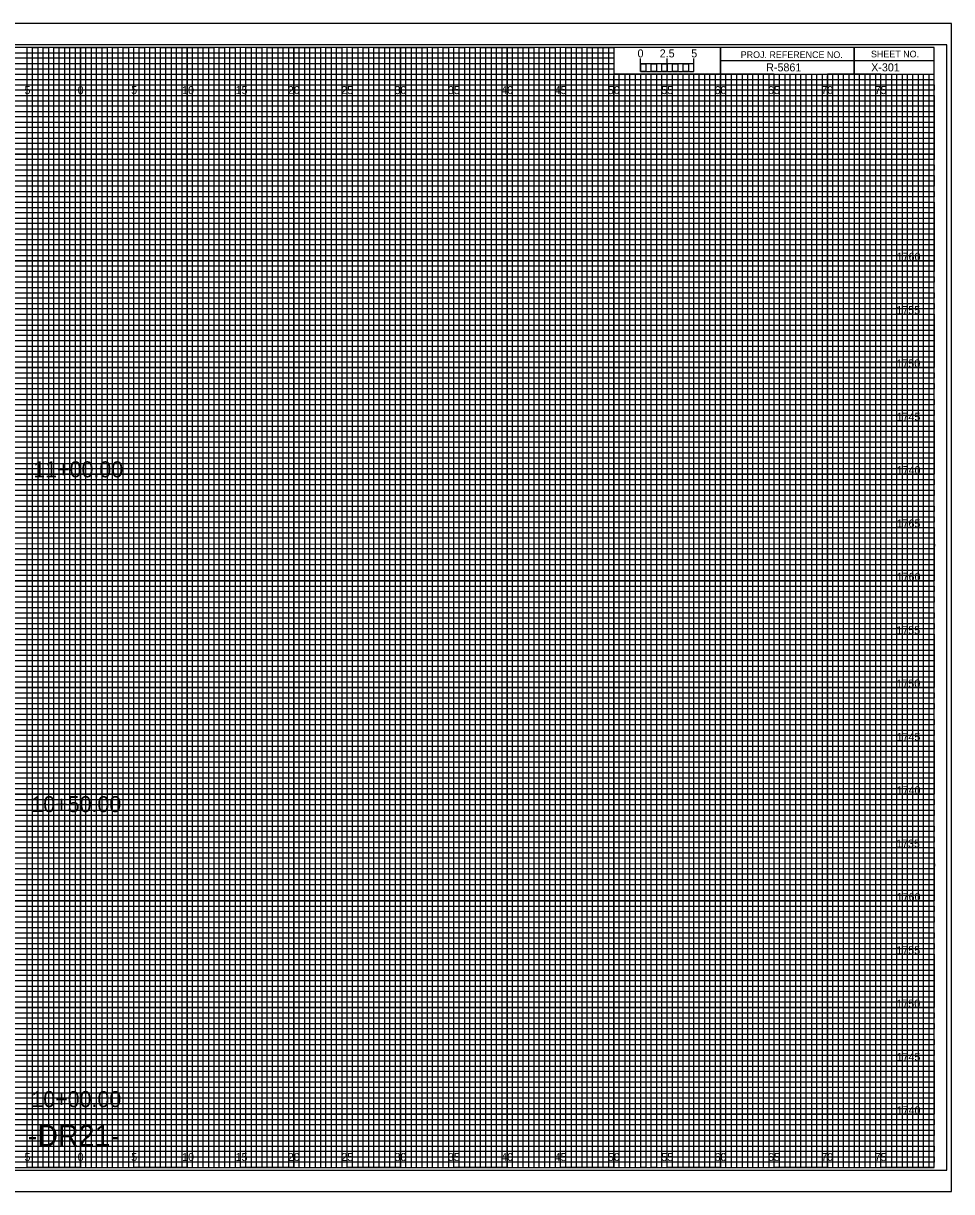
# Model space of a CAD drawing. Extents: x -7 to 162, y -2 to 107.
# Drawn here: x 74.6 to 161.7, y -2.3 to 107.3 of the extents above; entities that cross this region are included whole.
import ezdxf

# ---------------------------------------------------------------- set-up
doc = ezdxf.new("R2010")
doc.units = 0
for name, color, linetype in [('Prop XS Alignment Label', 7, 'Continuous'), ('Prop XS Bar Scale Labels', 7, 'Continuous'), ('Prop XS Elevation Labels', 7, 'Continuous'), ('Prop XS Offset Labels', 7, 'Continuous'), ('Prop XS Project Number', 7, 'Continuous'), ('Prop XS Sheet Number', 7, 'Continuous'), ('Prop XS Station Labels', 7, 'Continuous'), ('Sheet Cross Section CELL', 7, 'Continuous'), ('Sheet Cross Section Grid Major CELL', 7, 'Continuous'), ('Sheet Cross Section Grid Middle CELL', 7, 'Continuous'), ('Sheet Cross Section Grid Minor 1 CELL', 7, 'Continuous'), ('Sheet Cross Section Grid Minor 2 CELL', 7, 'Continuous'), ('Sheet Cross Section Scale CELL', 7, 'Continuous'), ('Sheet Cutting Line CELL', 7, 'Continuous'), ('Sheet DOT Grid CELL', 7, 'Continuous'), ('Sheet Plot Border Inside CELL', 7, 'Continuous'), ('Sheet Plot Border Outside CELL', 7, 'Continuous')]:
    doc.layers.add(name, color=color, linetype=linetype)

msp = doc.modelspace()

# ---------------------------------------------------------------- linework, layer by layer
at = {"layer": 'Sheet Cross Section CELL'}
for p, q in [((152.5, 105), (152.5, 102.5)), ((152.5, 102.5), (152.5, 105)), ((160, 103.75), (140, 103.75)), ((140, 103.75), (140, 102.5)), ((140, 102.5), (160, 102.5))]:
    msp.add_line(p, q, dxfattribs=at)
for points in [[(160, 105), (0, 105), (0, 0), (160, 0)], [(140, 105), (130, 105), (130, 102.52), (140, 102.52)], [(160, 105), (140, 105), (140, 102.5), (160, 102.5)]]:
    msp.add_lwpolyline(points, close=True, dxfattribs=at)
at = {"layer": 'Sheet Cross Section Grid Major CELL'}
for p, q in [((75, 105), (70, 105)), ((75, 0), (75, 105)), ((85, 105), (80, 105)), ((80, 105), (80, 0)), ((85, 0), (85, 105)), ((95, 105), (90, 105)), ((90, 105), (90, 0)), ((95, 0), (95, 105)), ((105, 105), (100, 105)), ((100, 105), (100, 0)), ((105, 0), (105, 105)), ((115, 105), (110, 105)), ((110, 105), (110, 0)), ((115, 0), (115, 105)), ((125, 105), (120, 105)), ((120, 105), (120, 0)), ((125, 0), (125, 105)), ((130, 105), (130, 0)), ((135, 0), (135, 102.5)), ((145, 102.5), (140, 102.5)), ((140, 102.5), (140, 0)), ((145, 0), (145, 102.5)), ((155, 102.5), (150, 102.5)), ((150, 102.5), (150, 0)), ((155, 0), (155, 102.5)), ((80, 0), (75, 0)), ((90, 0), (85, 0)), ((100, 0), (95, 0)), ((110, 0), (105, 0)), ((120, 0), (115, 0)), ((130, 0), (125, 0)), ((140, 0), (135, 0)), ((150, 0), (145, 0)), ((160, 0), (155, 0)), ((160, 0), (160, 0))]:
    msp.add_line(p, q, dxfattribs=at)
for points in [[(0, 100), (160, 100), (160, 95), (0, 95)], [(0, 90), (160, 90), (160, 85), (0, 85)], [(0, 80), (160, 80), (160, 75), (0, 75)], [(0, 70), (160, 70), (160, 65), (0, 65)], [(0, 60), (160, 60), (160, 55), (0, 55)], [(0, 50), (160, 50), (160, 45), (0, 45)], [(0, 40), (160, 40), (160, 35), (0, 35)], [(0, 30), (160, 30), (160, 25), (0, 25)], [(0, 20), (160, 20), (160, 15), (0, 15)], [(0, 10), (160, 10), (160, 5), (0, 5)]]:
    msp.add_lwpolyline(points, dxfattribs=at)
at = {"layer": 'Sheet Cross Section Grid Middle CELL'}
for points in [[(72.5, 0), (77.5, 0), (77.5, 105), (82.5, 105), (82.5, 0), (87.5, 0), (87.5, 105), (92.5, 105), (92.5, 0), (97.5, 0), (97.5, 105), (102.5, 105), (102.5, 0), (107.5, 0), (107.5, 105), (112.5, 105), (112.5, 0), (117.5, 0), (117.5, 105), (122.5, 105), (122.5, 0), (127.5, 0), (127.5, 105), (129.97, 105), (130, 105), (130, 102.5), (132.5, 102.5), (132.5, 0), (137.5, 0), (137.5, 102.5), (142.5, 102.5), (142.5, 0), (147.5, 0), (147.5, 102.5), (152.5, 102.5), (152.5, 0), (157.5, 0), (157.5, 102.5)], [(0, 102.5), (137.5, 102.5)], [(0, 92.5), (160, 92.5), (160, 97.5), (0, 97.5)], [(0, 82.5), (160, 82.5), (160, 87.5), (0, 87.5)], [(0, 72.5), (160, 72.5), (160, 77.5), (0, 77.5)], [(0, 62.5), (160, 62.5), (160, 67.5), (0, 67.5)], [(0, 52.5), (160, 52.5), (160, 57.5), (0, 57.5)], [(0, 42.5), (160, 42.5), (160, 47.5), (0, 47.5)], [(0, 32.5), (160, 32.5), (160, 37.5), (0, 37.5)], [(0, 22.5), (160, 22.5), (160, 27.5), (0, 27.5)], [(0, 12.5), (160, 12.5), (160, 17.5), (0, 17.5)], [(0, 2.5), (160, 2.5), (160, 7.5), (0, 7.5)]]:
    msp.add_lwpolyline(points, dxfattribs=at)
at = {"layer": 'Sheet Cross Section Grid Minor 1 CELL'}
for p, q in [((0, 104.5), (130, 104.5)), ((130, 104.5), (130, 103.99)), ((130, 103.99), (0, 103.99)), ((0, 103.5), (130, 103.5)), ((130, 102.95), (0, 102.95)), ((130, 103.5), (130, 102.95)), ((0, 102), (160, 102))]:
    msp.add_line(p, q, dxfattribs=at)
for points in [[(0, 101.5), (135, 101.5), (160, 101.5), (160, 101), (0, 101)], [(0, 100.5), (160, 100.5), (160, 99.5), (0, 99.5)], [(0, 99), (160, 99), (160, 98.5), (0, 98.49)], [(0, 98), (160, 98), (160, 97), (0, 97)], [(0, 96.5), (160, 96.5), (160, 96), (0, 96)], [(0, 95.5), (160, 95.5), (160, 94.5), (0, 94.5)], [(0, 94), (160, 94), (160, 93.5), (0, 93.5)], [(0, 93), (160, 93), (160, 92), (0, 92)], [(0, 91.5), (160, 91.5), (160, 91), (0, 91)], [(0, 90.5), (160, 90.5), (160, 89.5), (0, 89.5)], [(0, 89), (160, 89), (160, 88.5), (0, 88.5)], [(0, 88), (160, 88), (160, 86.98), (160, 86.5), (160, 86), (0, 86)], [(0, 87), (160, 87), (160, 86.5), (0, 86.5)], [(0, 85.5), (160, 85.5), (160, 84.5), (0, 84.52)], [(0, 84.52), (160, 84.5), (160, 84), (0, 84)], [(0, 83.5), (160, 83.5), (160, 83), (0, 83)], [(0, 82), (160, 82), (160, 81.5), (0, 81.5)], [(0, 81), (160, 81), (160, 80.5), (0, 80.5)], [(-0.04, 79.45), (160, 79.45), (160, 78.94), (-0.04, 78.94)], [(0, 78.5), (160, 78.5), (160, 78), (0, 78)], [(0, 77), (160, 77), (160, 76.5), (0, 76.5)], [(0, 76), (160, 76), (160, 75.5), (0, 75.5)], [(0, 74.5), (160, 74.5), (160, 74), (0, 74)], [(0, 73.5), (160, 73.5), (160, 73), (0, 73)], [(0, 72), (160, 72), (160, 71.5), (0, 71.5)], [(0, 71), (160, 71), (160, 70.5), (0, 70.5)], [(0, 69.5), (160, 69.5), (160, 68.99), (0, 69)], [(0, 68.5), (160, 68.5), (160, 68), (0, 68)], [(0, 67), (160, 67), (160, 66.5), (0, 66.5)], [(0, 66), (160, 66), (160, 65.5), (0, 65.5)], [(0, 64.5), (160, 64.5), (160, 64), (0, 64)], [(0, 63.5), (160, 63.5), (160, 63), (0, 63)], [(0, 62), (160, 62), (160, 61.5), (0, 61.5)], [(0, 61), (160, 61), (160, 60.5), (0, 60.5)], [(0, 59.5), (160, 59.5), (160, 59), (0, 59)], [(0, 58.5), (160.03, 58.45), (160, 58), (0, 58)], [(0, 57), (160, 57), (160, 56.5), (0, 56.5)], [(0, 56), (160, 56), (160, 55.5), (0, 55.5)], [(0, 54.5), (160, 54.5), (160, 54), (0, 54)], [(0, 53.5), (160, 53.5), (160, 53), (0, 53)], [(0, 52), (160, 52), (160, 51.5), (0, 51.5)], [(0, 51), (160, 51), (160, 50.5), (0, 50.5)], [(0, 49.5), (160, 49.5), (160, 49), (0, 49)], [(0, 48.5), (160, 48.5), (160, 48), (0, 48)], [(0, 47), (160, 47), (160, 46.5), (0, 46.5)], [(0, 46), (160, 46), (160, 45.5), (0, 45.5)], [(0, 44.5), (160, 44.5), (160, 44), (0, 44)], [(0, 43.5), (160, 43.5), (160, 43), (0, 43)], [(0, 42), (160, 42), (160, 41.5), (0, 41.5)], [(0, 41), (160, 41), (160, 40.5), (0, 40.5)], [(0, 39.5), (160, 39.5), (160, 38.99), (0, 39)], [(0, 38.5), (160, 38.5), (160, 38), (0, 38)], [(0, 37), (160, 37), (160, 36.5), (0, 36.5)], [(0, 36), (160, 36), (160, 35.5), (0, 35.5)], [(0, 34.5), (160, 34.5), (160, 34), (0, 34)], [(0, 33.5), (160, 33.5), (160, 33), (0, 33)], [(0, 32), (160, 32), (160, 31.5), (0, 31.5)], [(0, 31), (160, 31), (160, 30.5), (0, 30.5)], [(0, 29.5), (160, 29.5), (160, 29), (0, 29)], [(0, 28.5), (160.03, 28.46), (160, 28), (0, 28)], [(0, 27), (160, 27), (160, 26.5), (0, 26.5)], [(0, 26), (160, 26), (160, 25.5), (0, 25.5)], [(0, 24.5), (160, 24.5), (160, 24), (0, 24)], [(0, 23.5), (160, 23.5), (160, 23), (0, 23)], [(0, 22), (160, 22), (160, 21.5), (0, 21.5)], [(0, 21), (160, 21), (160, 20.5), (0, 20.5)], [(0, 19.5), (160, 19.5), (160, 19), (0, 19)], [(0, 18.5), (160, 18.5), (160, 18), (0, 18)], [(0, 17), (160, 17), (160, 16.5), (0, 16.5)], [(0, 16), (160, 16), (160, 15.5), (0, 15.5)], [(0, 14.5), (160, 14.5), (160, 14), (0, 14)], [(0, 13.5), (160, 13.5), (160, 13), (0, 13)], [(0, 12), (160, 12), (160, 11.5), (0, 11.5)], [(0, 11), (160, 11), (160, 10.5), (0, 10.5)], [(0, 9.5), (160, 9.5), (160, 9), (0, 9)], [(0, 8.5), (160, 8.5), (160, 8), (0, 8)], [(0, 7), (160, 7), (160, 6.5), (0, 6.5)], [(0, 6), (160, 6), (160, 5.5), (0, 5.5)], [(0, 4.5), (160, 4.5), (160, 4), (0, 4)], [(0, 3.5), (160, 3.5), (160, 3), (0, 3)], [(0, 2), (160, 2), (160, 1.5), (0, 1.5)], [(0, 1), (160, 1), (160, 0.5), (0, 0.5)]]:
    msp.add_lwpolyline(points, dxfattribs=at)
at = {"layer": 'Sheet Cross Section Grid Minor 2 CELL'}
for p, q in [((133.5, 102.5), (133, 102.5)), ((133, 102.5), (133, 0)), ((133.5, 0), (133.5, 102.5)), ((134.5, 102.5), (134, 102.5)), ((134, 102.5), (134, 0)), ((134.5, 0), (134.5, 102.5)), ((133, 0), (132.5, 0)), ((134, 0), (133.5, 0))]:
    msp.add_line(p, q, dxfattribs=at)
for points in [[(75, 0), (75.5, 0), (75.5, 105), (76, 105), (76, 0)], [(76, 0), (76.5, 0), (76.5, 105), (77, 105), (77, 0)], [(77.5, 0), (78, 0), (78, 105), (78.5, 105), (78.5, 0)], [(78.5, 0), (79, 0), (79, 105), (79.5, 105), (79.5, 0)], [(80, 0), (80.5, 0), (80.5, 105), (81, 105), (81, 0)], [(81, 0), (81.5, 0), (81.5, 105), (82, 105), (82, 0)], [(82.5, 0), (83, 0), (83, 105), (83.5, 105), (83.5, 0)], [(83.5, 0), (84, 0), (84, 105), (84.5, 105), (84.5, 0)], [(85, 0), (85.5, 0), (85.5, 105), (86, 105), (86, 0)], [(86, 0), (86.5, 0), (86.5, 105), (87, 105), (87, 0)], [(87.5, 0), (88, 0), (88, 105), (88.5, 105), (88.5, 0)], [(88.5, 0), (89, 0), (89, 105), (89.5, 105), (89.5, 0)], [(90, 0), (90.5, 0), (90.5, 105), (91, 105), (91, 0)], [(91, 0), (91.5, 0), (91.5, 105), (92, 105), (92, 0)], [(92.5, 0), (93, 0), (93, 105), (93.5, 105), (93.5, 0)], [(93.5, 0), (94, 0), (94, 105), (94.5, 105), (94.5, 0)], [(95, 0), (95.5, 0), (95.5, 105), (96, 105), (96, 0)], [(96, 0), (96.5, 0), (96.5, 105), (97, 105), (97, 0)], [(97.5, 0), (98, 0), (98, 105), (98.5, 105), (98.5, 0)], [(98.5, 0), (99, 0), (99, 105), (99.5, 105), (99.5, 0)], [(100, 0), (100.5, 0), (100.5, 105), (101, 105), (101, 0)], [(101, 0), (101.5, 0), (101.5, 105), (102, 105), (102, 0)], [(102.5, 0), (103, 0), (103, 105), (103.5, 105), (103.5, 0)], [(103.5, 0), (104, 0), (104, 105), (104.5, 105), (104.5, 0)], [(105, 0), (105.5, 0), (105.5, 105), (106, 105), (106, 0)], [(106, 0), (106.5, 0), (106.5, 105), (107, 105), (107, 0)], [(107.5, 0), (108, 0), (108, 105), (108.5, 105), (108.5, 0)], [(108.5, 0), (109, 0), (109, 105), (109.5, 105), (109.5, 0)], [(110, 0), (110.5, 0), (110.5, 105), (111, 105), (111, 0)], [(111, 0), (111.5, 0), (111.5, 105), (112, 105), (112, 0)], [(112.5, 0), (113, 0), (113, 105), (113.5, 105), (113.5, 0)], [(113.5, 0), (114, 0), (114, 105), (114.5, 105), (114.5, 0)], [(115, 0), (115.5, 0), (115.5, 105), (116, 105), (116, 0)], [(116, 0), (116.5, 0), (116.5, 105), (117, 105), (117, 0)], [(117.5, 0), (118, 0), (118, 105), (118.5, 105), (118.5, 0)], [(118.5, 0), (119, 0), (119, 105), (119.5, 105), (119.5, 0)], [(120, 0), (120.5, 0), (120.5, 105), (121, 105), (121, 0)], [(121, 0), (121.5, 0), (121.5, 105), (122, 105), (122, 0)], [(122.5, 0), (123, 0), (123, 105), (123.5, 105), (123.5, 0)], [(123.5, 0), (124, 0), (124, 105), (124.5, 105), (124.5, 0)], [(125, 0), (125.5, 0), (125.5, 105), (126, 105), (126, 0)], [(126, 0), (126.5, 0), (126.5, 105), (127, 105), (127, 0)], [(127.5, 0), (128, 0), (128, 105), (128.5, 105), (128.5, 0)], [(128.5, 0), (129, 0), (129, 105), (129.5, 105), (129.5, 0)], [(130, 0), (130.5, 0), (130.5, 102.5), (131.01, 102.5), (131.01, 0)], [(131, 0), (131.5, 0), (131.5, 102.5), (132, 102.5), (132, 0)], [(135, 0), (135.49, 0), (135.49, 102.5), (136, 102.5), (136, 0)], [(136, 0), (136.5, 0), (136.5, 102.5), (137.03, 102.5), (137.03, 0)], [(137.5, 0), (138, 0), (138, 102.5), (138.5, 102.5), (138.5, 0)], [(138.5, 0), (139, 0), (139, 102.5), (139.5, 102.5), (139.5, 0)], [(140, 0), (140.5, 0), (140.5, 102.5), (141, 102.5), (141, 0)], [(141, 0), (141.5, 0), (141.5, 102.5), (142, 102.5), (142, 0)], [(142.5, 0), (143, 0), (143, 102.5), (143.5, 102.5), (143.5, 0)], [(143.5, 0), (144, 0), (144, 102.5), (144.5, 102.5), (144.5, 0)], [(145, 0), (145.5, 0), (145.5, 102.5), (146, 102.5), (146, 0)], [(146, 0), (146.5, 0), (146.5, 102.5), (147, 102.5), (147, 0)], [(147.5, 0), (148, 0), (148, 102.5), (148.5, 102.5), (148.5, 0)], [(148.5, 0), (149, 0), (149, 102.5), (149.5, 102.5), (149.5, 0)], [(150, 0), (150.5, 0), (150.5, 102.5), (151, 102.5), (151, 0)], [(151, 0), (151.5, 0), (151.5, 102.5), (152, 102.5), (152, 0)], [(152.5, 0), (153, 0), (153, 102.5), (153.5, 102.5), (153.5, 0)], [(153.5, 0), (154, 0), (154, 102.5), (154.5, 102.5), (154.5, 0)], [(155, 0), (155.5, 0), (155.5, 102.5), (156, 102.5), (156, 0)], [(156, 0), (156.5, 0), (156.5, 102.5), (157, 102.5), (157, 0)], [(157.5, 0), (158, 0), (158, 102.5), (158.5, 102.5), (158.5, 0)], [(158.5, 0), (159, 0), (159, 102.5), (159.5, 102.5), (159.5, 0)]]:
    msp.add_lwpolyline(points, dxfattribs=at)
at = {"layer": 'Sheet Cross Section Scale CELL'}
for p, q in [((132.5, 102.75), (132.5, 103.95)), ((132.5, 103.45), (132.5, 103.95)), ((135, 102.75), (135, 103.95)), ((137.5, 102.75), (137.5, 103.95)), ((137.5, 103.45), (137.5, 103.95))]:
    msp.add_line(p, q, dxfattribs=at)
for points in [[(137.5, 103.45), (132.5, 103.45), (132.5, 102.75), (137.5, 102.75)], [(132.5, 103.45), (133, 103.45), (133, 102.75), (132.5, 102.75)], [(133.5, 103.45), (134, 103.45), (134, 102.75), (133.5, 102.75)], [(134.5, 103.45), (135, 103.45), (135, 102.75), (134.5, 102.75)], [(135.5, 103.45), (136, 103.45), (136, 102.75), (135.5, 102.75)], [(136.5, 103.45), (137, 103.45), (137, 102.75), (136.5, 102.75)]]:
    msp.add_lwpolyline(points, close=True, dxfattribs=at)
at = {"layer": 'Sheet Cutting Line CELL'}
for p, q in [((161.65, 107.25), (-6.7, 107.25)), ((-6.7, -2.25), (161.65, -2.25))]:
    msp.add_line(p, q, dxfattribs=at)
at = {"layer": 'Sheet DOT Grid CELL'}
for p, q in [((75, 0), (75, 105)), ((80, 0), (80, 105)), ((85, 0), (85, 105)), ((90, 0), (90, 105)), ((95, 0), (95, 105)), ((100, 0), (100, 105)), ((105, 0), (105, 105)), ((110, 0), (110, 105)), ((115, 0), (115, 105)), ((120, 0), (120, 105)), ((125, 0), (125, 105)), ((130, 0), (130, 102.34)), ((135, 0), (135, 102.34)), ((140, 0), (140, 102.34)), ((145, 0), (145, 102.34)), ((150, 0), (150, 102.34)), ((155, 0), (155, 102.34)), ((0, 100), (160, 100)), ((0, 95), (160, 95)), ((0, 90), (160, 90)), ((0, 85), (160, 85)), ((0, 80), (160, 80)), ((0, 75), (160, 75)), ((0, 70), (160, 70)), ((0, 65), (160, 65)), ((0, 60), (160, 60)), ((0, 55), (160, 55)), ((0, 50), (160, 50)), ((0, 45), (160, 45)), ((0, 40), (160, 40)), ((0, 35), (160, 35)), ((0, 30), (160, 30)), ((0, 25), (160, 25)), ((0, 20), (160, 20)), ((0, 15), (160, 15)), ((0, 10), (160, 10)), ((0, 5), (160, 5))]:
    msp.add_line(p, q, dxfattribs=at)
at = {"layer": 'Sheet Plot Border Inside CELL'}
msp.add_lwpolyline([(-5.4, -0.25), (161.2, -0.25), (161.2, 105.25), (-5.4, 105.25)], close=True, dxfattribs=at)
at = {"layer": 'Sheet Plot Border Outside CELL'}
msp.add_lwpolyline([(-6.7, -2.25), (161.65, -2.25), (161.65, 107.25), (-6.7, 107.25)], close=True, dxfattribs=at)

# ---------------------------------------------------------------- texts
at = {"layer": 'Prop XS Alignment Label'}
msp.add_text('-DR21-', height=2, dxfattribs=at).set_placement((75.06, 2))
at = {"layer": 'Prop XS Bar Scale Labels'}
for s, p in [('2.5', (134.29, 104.06)), ('5', (137.24, 104.06))]:
    msp.add_text(s, height=0.75, dxfattribs=at).set_placement(p)
at = {"layer": 'Prop XS Elevation Labels'}
for s, p in [('1760', (156.5, 85)), ('1755', (156.47, 80)), ('1750', (156.48, 75)), ('1745', (156.49, 70)), ('1740', (156.5, 65)), ('1765', (156.49, 60)), ('1760', (156.5, 55)), ('1755', (156.47, 50)), ('1750', (156.48, 45)), ('1745', (156.49, 40)), ('1740', (156.5, 35)), ('1735', (156.45, 30)), ('1760', (156.5, 25)), ('1755', (156.47, 20)), ('1750', (156.48, 15)), ('1745', (156.49, 10)), ('1740', (156.5, 5))]:
    msp.add_text(s, height=0.75, dxfattribs=at).set_placement(p)
at = {"layer": 'Prop XS Offset Labels'}
for s, p in [('5', (74.74, 100.62)), ('0', (79.73, 100.62)), ('0', (79.73, 100.62)), ('5', (84.74, 100.62)), ('10', (89.52, 100.62)), ('15', (94.53, 100.62)), ('20', (99.43, 100.62)), ('25', (104.44, 100.62)), ('30', (109.43, 100.62)), ('35', (114.44, 100.62)), ('40', (119.43, 100.62)), ('45', (124.44, 100.62)), ('50', (129.43, 100.62)), ('55', (134.44, 100.62)), ('60', (139.43, 100.62)), ('65', (144.44, 100.62)), ('70', (149.43, 100.62)), ('75', (154.44, 100.62)), ('5', (74.74, 0.62)), ('0', (79.73, 0.62)), ('0', (79.73, 0.62)), ('5', (84.74, 0.62)), ('10', (89.52, 0.62)), ('15', (94.53, 0.62)), ('20', (99.43, 0.62)), ('25', (104.44, 0.62)), ('30', (109.43, 0.62)), ('35', (114.44, 0.62)), ('40', (119.43, 0.62)), ('45', (124.44, 0.62)), ('50', (129.43, 0.62)), ('55', (134.44, 0.62)), ('60', (139.43, 0.62)), ('65', (144.44, 0.62)), ('70', (149.43, 0.62)), ('75', (154.44, 0.62))]:
    msp.add_text(s, height=0.75, dxfattribs=at).set_placement(p)
at = {"layer": 'Prop XS Project Number'}
msp.add_text('R-5861', height=0.75, dxfattribs=at).set_placement((144.27, 102.75))
at = {"layer": 'Prop XS Sheet Number'}
msp.add_text('X-301', height=0.75, dxfattribs=at).set_placement((154.11, 102.75))
at = {"layer": 'Prop XS Station Labels'}
for s, p in [('11+00.00', (75.57, 64.7)), ('10+50.00', (75.39, 33.32)), ('10+00.00', (75.39, 5.67))]:
    msp.add_text(s, height=1.5, dxfattribs=at).set_placement(p)
at = {"layer": 'Sheet Cross Section CELL'}
for s, p in [('PROJ. REFERENCE NO.', (141.88, 104)), ('SHEET NO.', (154.09, 104.06))]:
    msp.add_text(s, height=0.625, dxfattribs=at).set_placement(p)
at = {"layer": 'Sheet Cross Section Scale CELL'}
msp.add_text('0', height=0.75, dxfattribs=at).set_placement((132.21, 104.06))

doc.saveas('drawing.dxf')
